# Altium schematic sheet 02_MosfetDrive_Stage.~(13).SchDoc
size A4; SheetNumber: 2; SheetTotal: 2
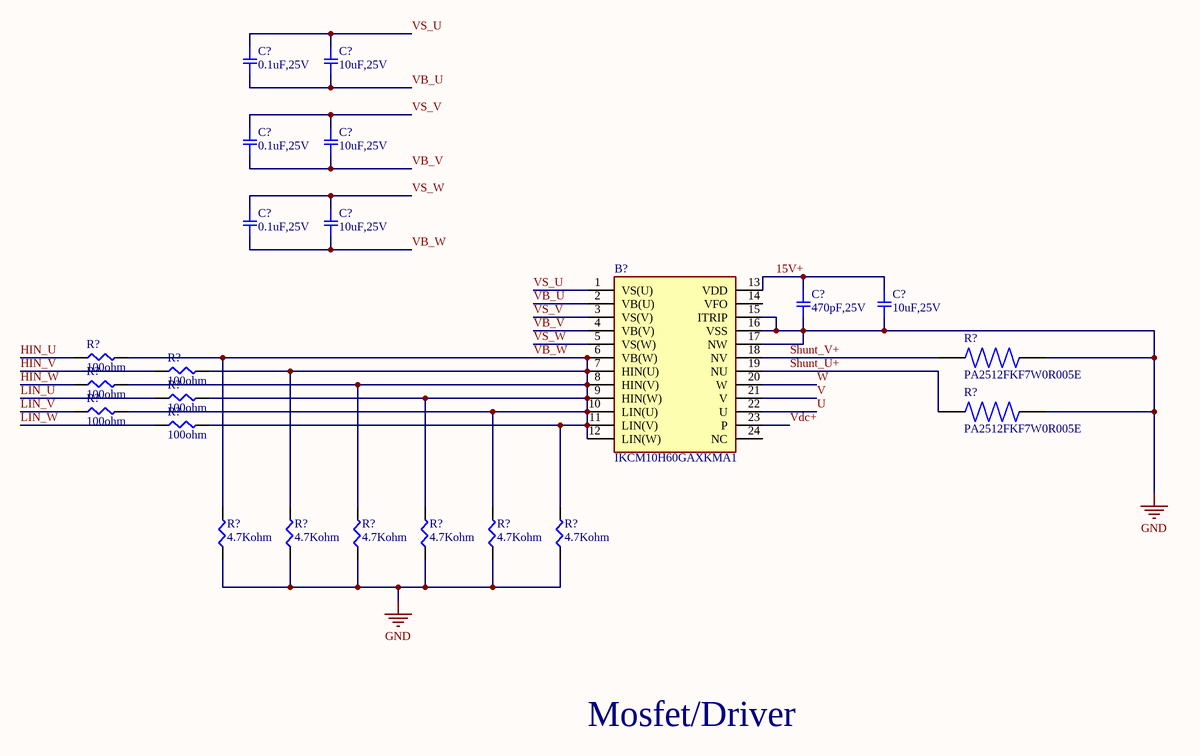
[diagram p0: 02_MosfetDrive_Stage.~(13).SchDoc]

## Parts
(Parts that share a designator on the sheet are numbered #1, #2 ... from top to bottom, then left to right.)
B?  IKCM10H60GAXKMA1  [997_IKCM10H60GAXKMA1]
C?#1  0.1uF,25V  [001_SMD-1206]
C?#2  10uF,25V  [001_SMD-1206]
C?#3  0.1uF,25V  [001_SMD-1206]
C?#4  10uF,25V  [001_SMD-1206]
C?#5  0.1uF,25V  [001_SMD-1206]
C?#6  10uF,25V  [001_SMD-1206]
C?#7  470pF,25V  [006_SMD_0605]
C?#8  10uF,25V  [006_SMD_0605]
R?#1  100ohm  [001_SMD-1206]
R?#2  PA2512FKF7W0R005E  [097_PA2512FKF7W0R005E]
R?#3  100ohm  [001_SMD-1206]
R?#4  100ohm  [001_SMD-1206]
R?#5  100ohm  [001_SMD-1206]
R?#6  100ohm  [001_SMD-1206]
R?#7  PA2512FKF7W0R005E  [097_PA2512FKF7W0R005E]
R?#8  100ohm  [001_SMD-1206]
R?#9  4.7Kohm  [001_SMD-1206]
R?#10  4.7Kohm  [001_SMD-1206]
R?#11  4.7Kohm  [001_SMD-1206]
R?#12  4.7Kohm  [001_SMD-1206]
R?#13  4.7Kohm  [001_SMD-1206]
R?#14  4.7Kohm  [001_SMD-1206]

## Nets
GND: B?.15(ITRIP) B?.16(VSS) B?.17(NW) C?#7.2 C?#8.2 R?#2.2 R?#7.2 R?#9.1 R?#10.1 R?#11.1 R?#12.1 R?#13.1 R?#14.1
15V+: B?.13(VDD) C?#7.1 C?#8.1
HIN_U: R?#1.1
HIN_V: R?#3.1
HIN_W: R?#4.1
LIN_U: R?#5.1
LIN_V: R?#6.1
LIN_W: R?#8.1
Shunt_U+: B?.19(NU) R?#7.1
Shunt_V+: B?.18(NV) R?#2.1
U: B?.22(U)
V: B?.21(V)
VB_U: B?.2(VB(U)) C?#1.2 C?#2.2
VB_V: B?.4(VB(V)) C?#3.2 C?#4.2
VB_W: B?.6(VB(W)) B?.7(HIN(U)) B?.8(HIN(V)) B?.9(HIN(W)) B?.10(LIN(U)) B?.11(LIN(V)) B?.12(LIN(W)) C?#5.2 C?#6.2 R?#1.2 R?#3.2 R?#4.2 R?#5.2 R?#6.2 R?#8.2 R?#9.2 R?#10.2 R?#11.2 R?#12.2 R?#13.2 R?#14.2
Vdc+: B?.23(P)
VS_U: B?.1(VS(U)) C?#1.1 C?#2.1
VS_V: B?.3(VS(V)) C?#3.1 C?#4.1
VS_W: B?.5(VS(W)) C?#5.1 C?#6.1
W: B?.20(W)

Not connected (* = marked no-connect by the designer): B? 14(VFO) 24(NC)

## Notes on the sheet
- Mosfet/Driver

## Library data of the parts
B? = IKCM10H60GAXKMA1: Intelligent Power Module 3-Ph 600V 10A; Manufacturer_Name: Infineon; Geometry.Height: 5.6mm
C?#1-C?#6 = C_1206_Template: CAP CER 1206; Part Number: GC321AD72E103KX01D; Manufacturer: Murata Electronics North America; Factory Stock: 0; Unit Price (USD): 0.3; Minimum Quantity: 1; Value: 10000pF; Tolerance: ±10%; Voltage: 250V; Temperature Coefficient: X7T
C?#7 C?#8 = C_0605_Template: CAP CER 0605; Part Number: GC321AD72E103KX01D; Manufacturer: Murata Electronics North America; Factory Stock: 0; Unit Price (USD): 0.3; Minimum Quantity: 1; Value: 10000pF; Tolerance: ±10%; Voltage: 250V; Temperature Coefficient: X7T
R?#1 R?#3-R?#6 R?#8-R?#14 = R_1206_Template: RES SMD 1206; Part Number: ERJ-8BQF1R0V; Manufacturer: Panasonic Electronic Components; Factory Stock: 0; Unit Price (USD): 0.05778; @ qty: 1500; Minimum Quantity: 1; Value: 1; Tolerance: ±1%; Power (Watts): 0.5W, 1/2W; Temperature Coefficient: ±200ppm/°C
R?#2 R?#7 = PA2512FKF7W0R005E: 5 mΩ, 2 W, ±1% current-sense shunt resistor, 2512 (6332 metric) SMD package, low-resistance metal-element construction.; MF: Bourns; MP: CRF2512-FZ-R005ELF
